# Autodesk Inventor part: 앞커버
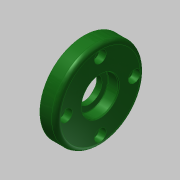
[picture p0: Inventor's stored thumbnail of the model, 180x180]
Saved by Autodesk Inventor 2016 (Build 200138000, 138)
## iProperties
Created: 2015-11
Part Number: 앞커버
Material: 알루미늄 6061
Document SubType Name: Modeling
Designer: mduedu
Density: 1 g/cm^3
Appearance: 매끄러움 - 짙은 산림 녹색
Author: mduedu
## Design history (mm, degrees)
sketch "스케치5"
  geometry: C1 r 30 at (0, 0); 2 further points
  constraints: 2 coincident, 1 centre point
  dimensions: "d66" = 60 diameter of C1
extrude "돌출2" new body sketch "스케치5" distance "d67" = 11; taper "d68" = 0 deg
sketch "스케치6"
  geometry: C1 r 16 at (0, 0); 1 further point
  constraints: 1 centre point, 1 coincident
  dimensions: "d69" = 32 diameter of C1
extrude "돌출3" join sketch "스케치6" distance "d70" = 3; taper "d71" = 0 deg
hole "구멍7" diameter "d98" = 25; stored, may be unused: countersink angle "d102" = 90 deg, drill point angle "d104" = 0 deg; dims "d96" = 10, "d97" = 10, "d99" = 6, "d100" = 4, "d101" = 2, "d103" = 3
hole "구멍8" diameter "d107" = 25; stored, may be unused: countersink angle "d111" = 90 deg, drill point angle "d113" = 0 deg; dims "d108" = 6, "d109" = 4, "d110" = 2, "d112" = 7.3, "d143" = 10, "d144" = 10
hole "구멍9" diameter "d116" = 17; stored, may be unused: countersink angle "d120" = 90 deg, drill point angle "d122" = 0 deg; dims "d114" = 10, "d115" = 10, "d117" = 6, "d118" = 4, "d119" = 2, "d121" = 7.7
chamfer "모따기2" distance "d123" = 0.7; stored, may be unused: second distance "d124" = 2, angle "d125" = 30 deg
fillet "모깎기11" dims "d126" = 0.3
fillet "모깎기13" dims "d128" = 3
fillet "모깎기14" dims "d129" = 3
fillet "모깎기15" dims "d130" = 0.3
sketch "스케치8" dims "d131" = 46
  geometry: 3 further points
  constraints: 2 vertical alignment, 1 coincident, 2 other
hole "구멍10" sketch "스케치8" at (0, 23) diameter "d132" = 4.5; stored, may be unused: countersink angle "d136" = 90 deg, drill point angle "d138" = 0 deg; dims "d133" = 6, "d134" = 8, "d135" = 4.6, "d137" = 7.7
node "솔리드2"
pattern_circular "원형 패턴4" dims angle "d140" = 360 deg
